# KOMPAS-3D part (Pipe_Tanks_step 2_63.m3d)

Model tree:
1. X Axis
2. Y Axis
3. Z Axis  (labels: Pipe Dn 50)
     Òîëùèíà ñòåíêè 1 = 1

Referenced files in C:\Documents and Settings\kashirsky\Мои документы\Camtasia Studio\Pipelines3D\Tanks\: Tanks_step 2.a3d
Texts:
  Pipe Dn 50
  Steel ASTM A295
  Three Point Plane
  Plane at Angle
  Line and Point Plane
  Axis through Two Vertices
  Axis of Feature
  Axis of Conical Surface
  Axis through Edge
  Trim by Surface
  Trim by Sketch
  Feature with No History
  Intersection Axis of Two Planes
  Two Line Plane
  Line and Face Plane
  Bend by line
  Hole in sheet body
  Cut in sheet body
  Point in CM
  Linear Dimension from Line to Point
  Surface Finish Symbol
  Geometric Tolerance Symbol
  Leader #1
  Leader #2
  Leader #3
  Shape Deviations and Datum
  Node point number
  Mark of coordination axis
  Node point designation
  Mark/Reference designation with leader
  Mark/reference designation on line
  Mark/Reference designation without leader
  Plane of section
